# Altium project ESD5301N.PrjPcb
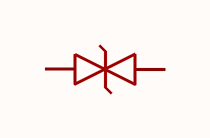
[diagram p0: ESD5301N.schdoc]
1 sheet, 1 parts. Net scope: global (net labels, ports and power ports of the same name join across sheets).

## Sheet ESD5301N.schdoc
size 127 x 101 mm

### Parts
D?  esd5301n  [DFN1006-2L_L1.0-W0.6-P0.70-BI]  (value not drawn)

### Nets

Not connected (* = marked no-connect by the designer): D? 1 2

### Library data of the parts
D? = esd5301n: 反向截止电压(Vrwm):5V;钳位电压:25V;峰值脉冲电流(Ipp):3A@8/20us;峰值脉冲功率(Ppp):50W@8/20us;击穿电压(VBR):8.5V;; Manufacturer: JSMSEMI(杰盛微); AddInBom: yes; ModelId: 8799f5d6b8214f9296437c35b5df300c; ModelName: DFN1006-2L_L1.0-W0.6-H0.5; ModelTransform: 39.37,23.622,0,0,0,0,0,0,0; Reverse Stand-Off Voltage (Vrwm): 5V; Clamping Voltage: 25V; Voltage - Breakdown: 8.5V; Reverse Leakage Current (Ir): 1uA; Number of Channels: 单路; level of protection: IEC 61000-4-2; Type: ESD; Junction Capacitance: 0.8pF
